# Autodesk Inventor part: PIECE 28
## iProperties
Created: 2004-11
Part Number: PIECE 28
Document SubType Name: Modeling
Designer: Bruno
Manufacturer: Standard
Standards Organization: Custom
Author: Bruno
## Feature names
1. Base1
